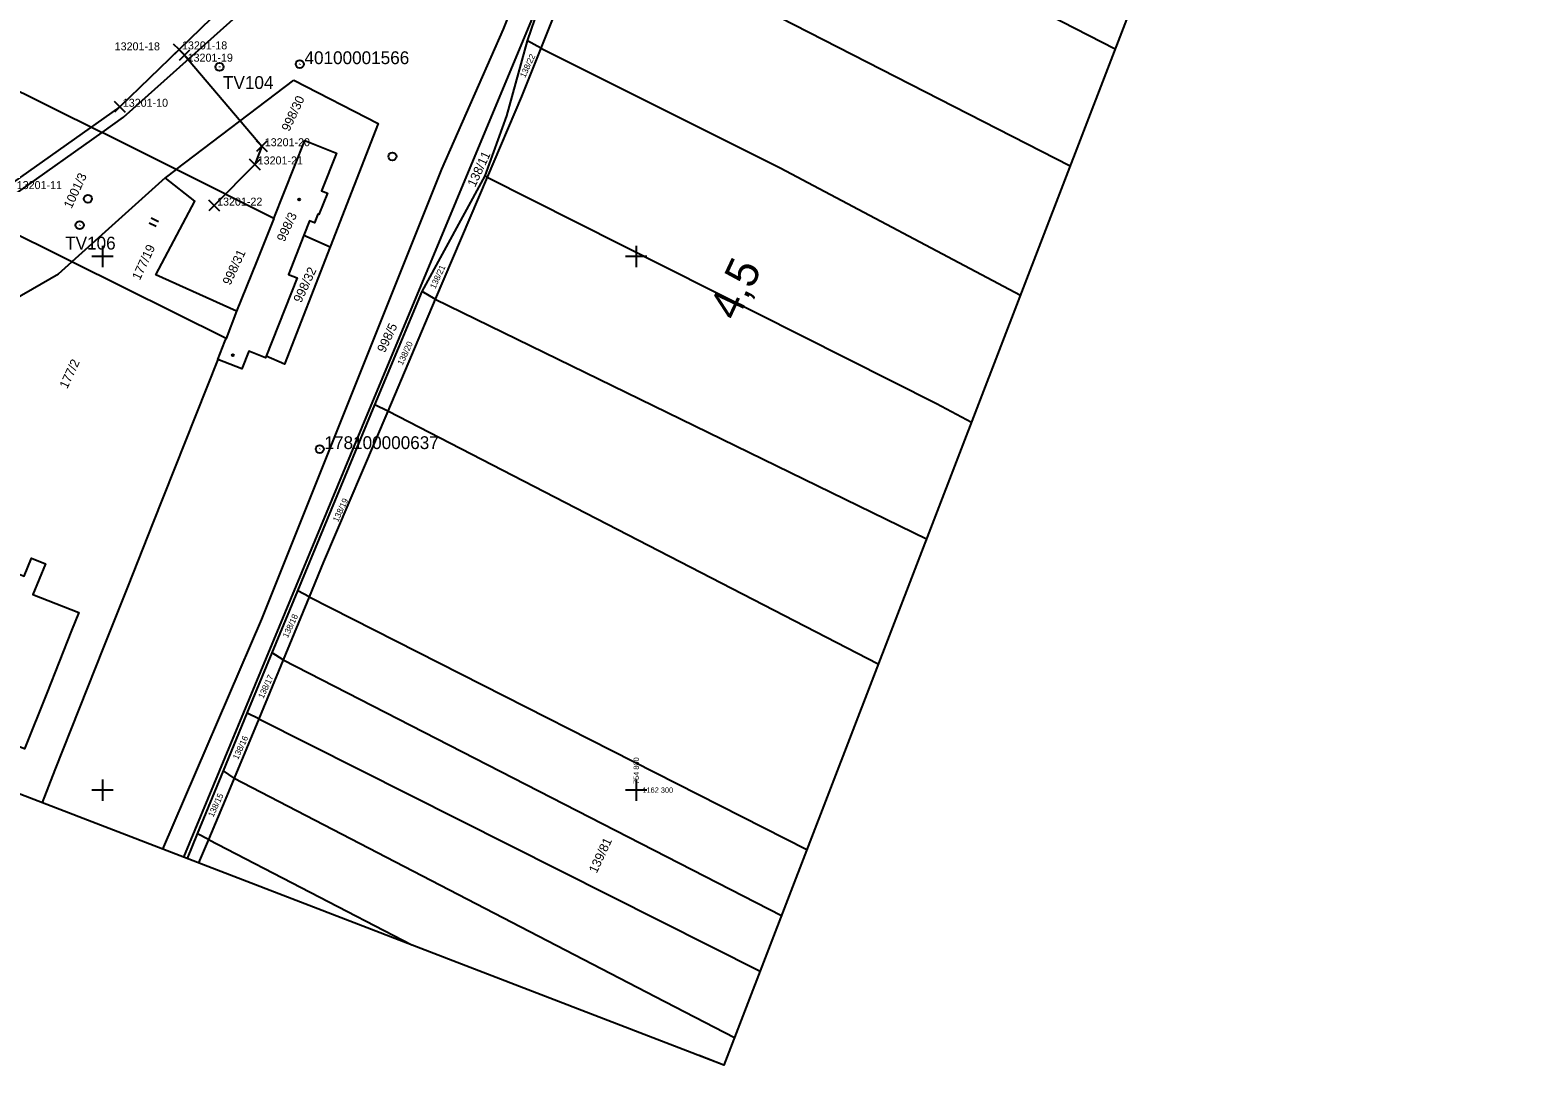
# Model space of a CAD drawing. Extents: x -755061 to -754557, y -1162352 to -1161657.
# Drawn here: x -754913.6 to -754632.7, y -1162351.5 to -1162157.5 of the extents above; entities that cross this region are included whole.
import ezdxf

# ---------------------------------------------------------------- set-up
doc = ezdxf.new("R2010")
doc.units = 0
for name, color, linetype in [('Body ŽBP', 7, 'Continuous'), ('Formát', 7, 'Continuous'), ('Katastrální hranice', 7, 'Continuous'), ('SO_01_32_01', 7, 'Continuous'), ('Staniceni a namezniky', 7, 'Continuous'), ('Síť', 7, 'Continuous'), ('VB_01_32_01', 7, 'Continuous'), ('Vrstva 55', 7, 'Continuous'), ('Vrstva 57', 7, 'Continuous'), ('Vrstva 58', 7, 'Continuous'), ('Vrstva 59', 7, 'Continuous')]:
    doc.layers.add(name, color=color, linetype=linetype)

msp = doc.modelspace()

# ---------------------------------------------------------------- linework, layer by layer
at = {"layer": 'Body ŽBP'}
for p, q in [((-754878.07, -1162164.41), (-754878.11, -1162164.5)), ((-754878.09, -1162164.46), (-754878.09, -1162164.46)), ((-754863.04, -1162163.89), (-754863.08, -1162163.99)), ((-754863.06, -1162163.94), (-754863.06, -1162163.94)), ((-754904.27, -1162194.08), (-754904.31, -1162194.17)), ((-754904.29, -1162194.12), (-754904.29, -1162194.12)), ((-754859.29, -1162236.03), (-754859.33, -1162236.13)), ((-754859.31, -1162236.08), (-754859.31, -1162236.08))]:
    msp.add_line(p, q, dxfattribs=at)
for centre in [(-754878.09, -1162164.46), (-754863.06, -1162163.94), (-754904.29, -1162194.12), (-754859.31, -1162236.08)]:
    msp.add_circle(centre, 0.756, dxfattribs=at)
at = {"layer": 'Formát'}
msp.add_line((-754783.57, -1162351.52), (-754788.23, -1162349.72), dxfattribs=at)
msp.add_lwpolyline([(-754909.9, -1161852.87), (-754632.71, -1161959.54), (-754783.57, -1162351.52), (-755060.75, -1162244.84)], close=True, dxfattribs=at)
at = {"layer": 'Katastrální hranice'}
msp.add_lwpolyline([(-754816.22, -1162147.35), (-754851.45, -1162231.96), (-754884.82, -1162312.55)], dxfattribs=at)
at = {"layer": 'SO_01_32_01'}
for points in [[(-754758.34, -1161933.06), (-754762.34, -1161937.68), (-754763.29, -1161936.85), (-754776.47, -1161949.62), (-754777.37, -1161978.41), (-754796.3, -1162026.28), (-754809.87, -1162057.58), (-754831.07, -1162091.65), (-754857.54, -1162133.93), (-754885.68, -1162161.18), (-754896.77, -1162171.93), (-754916.86, -1162186.18), (-754942.05, -1162200.54), (-754965.03, -1162211.64), (-754990.89, -1162220.78), (-755014.11, -1162227.27), (-755008.76, -1162253.14), (-755005.05, -1162256.17)], [(-754885.68, -1162161.18), (-754884.64, -1162162.26), (-754870.17, -1162179.33), (-754871.49, -1162182.74), (-754879.1, -1162190.46)]]:
    msp.add_lwpolyline(points, dxfattribs=at)
at = {"layer": 'Staniceni a namezniky'}
for centre in [(-754845.69, -1162181.24), (-754902.74, -1162189.18)]:
    msp.add_circle(centre, 0.75, dxfattribs=at)
at = {"layer": 'Síť'}
for points in [[(-754900, -1162198), (-754900, -1162200), (-754900, -1162202)], [(-754800, -1162198), (-754800, -1162200), (-754800, -1162202)], [(-754898, -1162200), (-754900, -1162200), (-754902, -1162200)], [(-754798, -1162200), (-754800, -1162200), (-754802, -1162200)], [(-754898, -1162300), (-754900, -1162300), (-754902, -1162300)], [(-754900, -1162298), (-754900, -1162300), (-754900, -1162302)], [(-754798, -1162300), (-754800, -1162300), (-754802, -1162300)], [(-754800, -1162298), (-754800, -1162300), (-754800, -1162302)]]:
    msp.add_lwpolyline(points, dxfattribs=at)
at = {"layer": 'VB_01_32_01'}
for p, q in [((-754885.68, -1162161.18), (-754886.68, -1162160.18)), ((-754885.68, -1162161.18), (-754886.68, -1162160.18)), ((-754885.68, -1162161.18), (-754886.68, -1162162.18)), ((-754885.68, -1162161.18), (-754886.68, -1162162.18)), ((-754885.68, -1162161.18), (-754884.68, -1162160.18)), ((-754885.68, -1162161.18), (-754884.68, -1162160.18)), ((-754885.68, -1162161.18), (-754884.68, -1162162.18)), ((-754885.68, -1162161.18), (-754884.68, -1162162.18)), ((-754884.64, -1162162.26), (-754885.64, -1162161.26)), ((-754884.64, -1162162.26), (-754885.64, -1162163.26)), ((-754884.64, -1162162.26), (-754883.64, -1162161.26)), ((-754884.64, -1162162.26), (-754883.64, -1162163.26)), ((-754896.77, -1162171.93), (-754897.77, -1162170.93)), ((-754896.77, -1162171.93), (-754895.77, -1162170.93)), ((-754896.77, -1162171.93), (-754897.77, -1162172.93)), ((-754896.77, -1162171.93), (-754895.77, -1162172.93)), ((-754870.17, -1162179.33), (-754871.17, -1162178.33)), ((-754870.17, -1162179.33), (-754871.17, -1162180.33)), ((-754870.17, -1162179.33), (-754869.17, -1162178.33)), ((-754870.17, -1162179.33), (-754869.17, -1162180.33)), ((-754871.49, -1162182.74), (-754872.49, -1162181.74)), ((-754871.49, -1162182.74), (-754870.49, -1162181.74)), ((-754871.49, -1162182.74), (-754872.49, -1162183.74)), ((-754871.49, -1162182.74), (-754870.49, -1162183.74)), ((-754879.1, -1162190.46), (-754880.1, -1162189.46)), ((-754879.1, -1162190.46), (-754880.1, -1162191.46)), ((-754879.1, -1162190.46), (-754878.1, -1162189.46)), ((-754879.1, -1162190.46), (-754878.1, -1162191.46))]:
    msp.add_line(p, q, dxfattribs=at)
at = {"layer": 'Vrstva 55'}
for p, q in [((-755012.97, -1162120.69), (-754900.06, -1162176.77)), ((-754808.43, -1162137.05), (-754817.91, -1162160.94)), ((-754820.38, -1162159.55), (-754816.22, -1162147.35)), ((-754817.91, -1162160.94), (-754820.38, -1162159.55)), ((-754886.23, -1162183.69), (-754864.19, -1162166.97)), ((-754886.23, -1162183.69), (-754900.06, -1162176.77)), ((-754886.23, -1162183.69), (-754888.26, -1162185.23)), ((-754867.91, -1162192.86), (-754886.23, -1162183.69)), ((-754840.13, -1162206.56), (-754828.31, -1162184.9)), ((-754827.93, -1162185.11), (-754828.31, -1162184.9)), ((-754888.26, -1162185.23), (-754905.78, -1162201)), ((-754827.93, -1162185.11), (-754837.67, -1162208.02)), ((-754905.78, -1162201), (-754923.5, -1162192.2)), ((-754862.27, -1162196.01), (-754857.37, -1162198.21)), ((-754876.85, -1162215.37), (-754905.78, -1162201)), ((-754848.96, -1162227.81), (-754840.13, -1162206.56)), ((-754837.67, -1162208.02), (-754840.13, -1162206.56)), ((-754874.91, -1162210.24), (-754876.85, -1162215.37)), ((-754837.67, -1162208.02), (-754846.58, -1162228.99)), ((-754863.44, -1162262.66), (-754848.96, -1162227.81)), ((-754846.58, -1162228.99), (-754848.96, -1162227.81)), ((-754868.25, -1162274.25), (-754863.44, -1162262.66)), ((-754861.29, -1162263.76), (-754863.44, -1162262.66)), ((-754861.29, -1162263.76), (-754866.17, -1162275.57)), ((-754872.9, -1162285.56), (-754868.25, -1162274.25)), ((-754866.17, -1162275.57), (-754868.25, -1162274.25)), ((-754866.17, -1162275.57), (-754870.74, -1162286.62)), ((-754877.36, -1162296.41), (-754872.9, -1162285.56)), ((-754870.74, -1162286.62), (-754872.9, -1162285.56)), ((-754870.74, -1162286.62), (-754875.34, -1162297.75)), ((-754882.21, -1162308.21), (-754877.36, -1162296.41)), ((-754875.34, -1162297.75), (-754877.36, -1162296.41)), ((-754884.11, -1162312.82), (-754882.21, -1162308.21)), ((-754880.18, -1162309.28), (-754882.21, -1162308.21)), ((-754880.18, -1162309.28), (-754882.02, -1162313.63)), ((-754880.18, -1162309.28), (-754842.03, -1162329.02))]:
    msp.add_line(p, q, dxfattribs=at)
for points in [[(-754888.68, -1162311.07), (-754870.17, -1162267.96), (-754836.4, -1162183.6), (-754824.89, -1162157.4), (-754808.97, -1162117.64), (-754790.52, -1162068.93), (-754761.32, -1161999.17), (-754754.27, -1161988.55)], [(-754799.86, -1162115.47), (-754745.23, -1162143.07), (-754710.27, -1162161.07)], [(-754808.43, -1162137.05), (-754718.71, -1162183.01)], [(-754816.22, -1162147.35), (-754851.45, -1162231.96), (-754884.82, -1162312.55)], [(-754816.22, -1162147.35), (-754851.45, -1162231.96), (-754884.82, -1162312.55)], [(-754900.06, -1162176.77), (-754896.07, -1162173.88), (-754868.56, -1162149.23)], [(-754828.31, -1162184.9), (-754824.25, -1162173.6), (-754820.38, -1162159.55)], [(-754817.91, -1162160.94), (-754821.51, -1162170), (-754827.93, -1162185.11)], [(-754817.91, -1162160.94), (-754773.06, -1162183.36), (-754728.03, -1162207.21)], [(-754864.19, -1162166.97), (-754848.34, -1162175.05), (-754857.37, -1162198.21)], [(-754923.5, -1162192.2), (-754915.78, -1162187.87), (-754900.06, -1162176.77)], [(-754867.91, -1162192.86), (-754862.1, -1162178.26), (-754856.15, -1162180.61), (-754858.96, -1162187.7), (-754857.88, -1162188.11), (-754859.46, -1162192.12), (-754859.66, -1162192.04), (-754860.31, -1162193.68), (-754861.2, -1162193.33), (-754862.27, -1162196.01)], [(-754874.91, -1162210.24), (-754890.05, -1162203.42), (-754882.73, -1162189.61), (-754888.26, -1162185.23)], [(-754827.93, -1162185.11), (-754743.71, -1162227.55), (-754737.2, -1162231.03)], [(-754867.91, -1162192.86), (-754871.15, -1162201.02), (-754874.91, -1162210.24)], [(-754862.27, -1162196.01), (-754865.18, -1162203.36), (-754863.54, -1162204.02), (-754869.36, -1162218.68)], [(-754857.37, -1162198.21), (-754865.94, -1162220.19), (-754869.36, -1162218.68)], [(-754971.15, -1162234.1), (-754958.95, -1162230.19), (-754951.07, -1162227.67), (-754947.14, -1162225.65), (-754943.74, -1162223.69), (-754908.27, -1162203.24), (-754905.78, -1162201)], [(-754837.67, -1162208.02), (-754745.6, -1162252.88)], [(-754878.41, -1162219.27), (-754877.09, -1162215.93), (-754876.85, -1162215.37)], [(-754869.36, -1162218.68), (-754869.47, -1162218.96), (-754872.61, -1162217.71), (-754873.93, -1162221.05), (-754878.41, -1162219.27)], [(-754878.41, -1162219.27), (-754890.63, -1162250.1), (-754895.21, -1162261.65), (-754899.8, -1162273.21), (-754904.37, -1162284.73), (-754908.92, -1162296.21), (-754911.35, -1162302.34)], [(-754846.58, -1162228.99), (-754858.59, -1162257.23), (-754861.29, -1162263.76)], [(-754754.65, -1162276.39), (-754846.58, -1162228.99)], [(-754922.63, -1162261.43), (-754921.01, -1162257.39), (-754914.72, -1162259.89), (-754913.29, -1162256.54), (-754910.69, -1162257.6), (-754913.05, -1162263.33), (-754904.47, -1162266.73), (-754905.81, -1162270.11), (-754910.45, -1162281.8), (-754914.62, -1162292.29), (-754930, -1162286.19), (-754925.41, -1162274.6), (-754922.38, -1162266.96), (-754924.5, -1162266.11), (-754922.63, -1162261.43)], [(-754861.29, -1162263.76), (-754768.03, -1162311.14)], [(-754866.17, -1162275.57), (-754772.78, -1162323.49)], [(-754870.74, -1162286.62), (-754776.8, -1162333.94)], [(-754875.34, -1162297.75), (-754877.03, -1162301.83), (-754880.18, -1162309.28)], [(-754875.34, -1162297.75), (-754796.43, -1162338.66), (-754781.59, -1162346.38)]]:
    msp.add_lwpolyline(points, dxfattribs=at)
at = {"layer": 'Vrstva 58'}
for p, q in [((-754889.52, -1162193.47), (-754890.88, -1162192.84)), ((-754889.95, -1162194.38), (-754891.3, -1162193.74))]:
    msp.add_line(p, q, dxfattribs=at)
at = {"layer": 'Vrstva 59'}
for centre in [(-754863.16, -1162189.31), (-754875.58, -1162218.5)]:
    msp.add_circle(centre, 0.175, dxfattribs=at)

# ---------------------------------------------------------------- texts
at = {"layer": 'Body ŽBP'}
for s, p in [(' 40100001566', (-754863.06, -1162163.94)), (' TV104', (-754878.33, -1162168.59)), (' TV106', (-754907.9, -1162198.69)), (' 178100000637', (-754859.31, -1162236.08))]:
    msp.add_text(s, height=2.4, dxfattribs=at).set_placement(p)
at = {"layer": 'Staniceni a namezniky'}
msp.add_text('4,5', height=6, rotation=64.9752, dxfattribs=at).set_placement((-754781.13, -1162212.3))
at = {"layer": 'Síť'}
msp.add_text('   754 800', height=1, rotation=90, dxfattribs=at).set_placement((-754799.5, -1162300))
msp.add_text('   1162 300', height=1, dxfattribs=at).set_placement((-754800, -1162300.5))
at = {"layer": 'VB_01_32_01'}
for s, p in [(' 13201-18', (-754885.68, -1162161.18)), (' 13201-18', (-754898.29, -1162161.36)), (' 13201-19', (-754884.62, -1162163.48)), (' 13201-10', (-754896.77, -1162171.93)), (' 13201-20', (-754870.17, -1162179.33)), (' 13201-21', (-754871.49, -1162182.74)), (' 13201-11', (-754916.64, -1162187.36)), (' 13201-22', (-754879.1, -1162190.46))]:
    msp.add_text(s, height=1.5, dxfattribs=at).set_placement(p)
at = {"layer": 'Vrstva 57'}
for s, height, p in [('138/22', 1.139, (-754820.83, -1162166.6)), ('998/30', 1.7, (-754865.03, -1162176.68)), ('138/11', 1.7, (-754830.19, -1162187.1)), ('1001/3', 1.7, (-754905.83, -1162191.15)), ('998/3', 1.7, (-754865.92, -1162197.37)), ('177/19', 1.7, (-754893.02, -1162204.56)), ('998/31', 1.7, (-754876.08, -1162205.5)), ('138/21', 1.139, (-754837.68, -1162206.16)), ('998/32', 1.7, (-754862.8, -1162208.8)), ('998/5', 1.7, (-754847.11, -1162218.14)), ('138/20', 1.139, (-754843.79, -1162220.47)), ('177/2', 1.7, (-754906.63, -1162224.9)), ('138/19', 1.139, (-754855.89, -1162249.86)), ('138/18', 1.139, (-754865.3, -1162271.57)), ('138/17', 1.139, (-754869.88, -1162282.94)), ('138/16', 1.139, (-754874.63, -1162294.37)), ('138/15', 1.139, (-754879.27, -1162305.16)), ('139/81', 1.7, (-754807.43, -1162315.72))]:
    msp.add_text(s, height=height, rotation=65, dxfattribs=at).set_placement(p)

doc.saveas('drawing.dxf')
